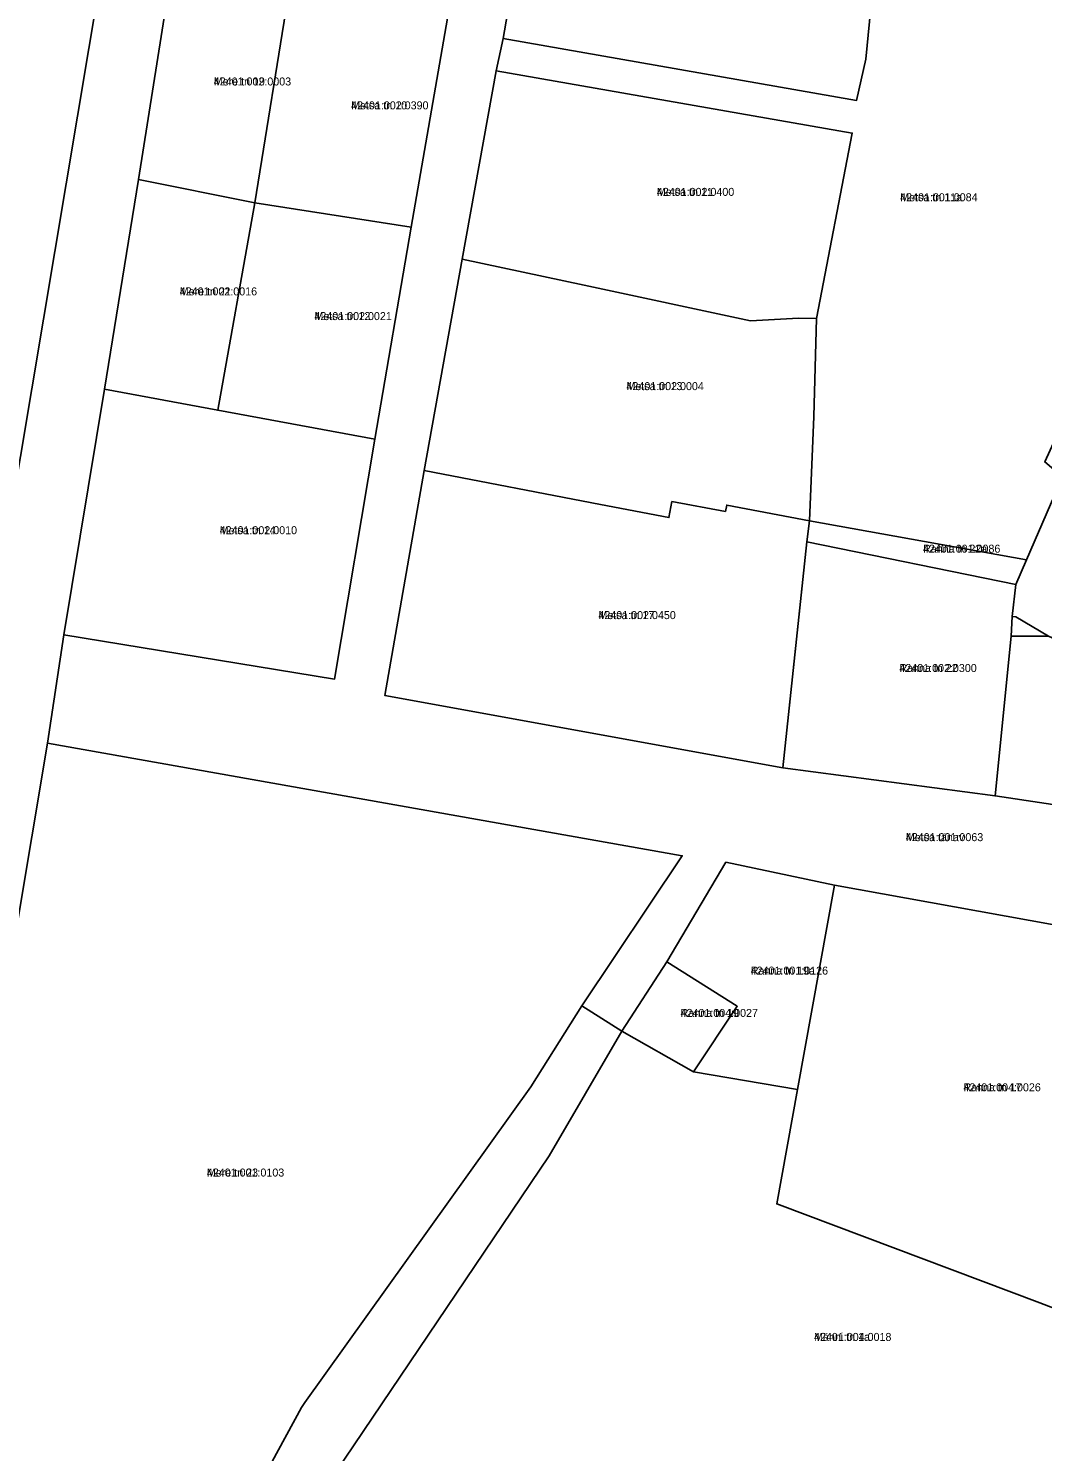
# Model space of a CAD drawing. Extents: x 595979 to 597983, y 6604231 to 6607350.
# Drawn here: x 596596.1 to 596786.2, y 6605469.2 to 6605736 of the extents above; entities that cross this region are included whole.
import ezdxf

# ---------------------------------------------------------------- set-up
doc = ezdxf.new("R2010")
doc.units = 0
for name, color, linetype in [('L_AADRESS', 7, 'Continuous'), ('PIIR', 7, 'Continuous'), ('TUNNUS', 7, 'Continuous')]:
    doc.layers.add(name, color=color, linetype=linetype)

msp = doc.modelspace()

# ---------------------------------------------------------------- linework, layer by layer
at = {"layer": 'PIIR'}
for points in [[(596695.91, 6606173.63), (596664.52, 6605976.79), (596663.07, 6605967.51), (596659.94, 6605968.22), (596650.85, 6605916.95), (596645.72, 6605885.35), (596645.06, 6605877.39), (596636.6, 6605826.7), (596630.08, 6605789.08), (596622.92, 6605747.16), (596616.69, 6605707.7), (596610.34, 6605668.35), (596602.72, 6605622.28), (596599.67, 6605601.99), (596540.44, 6605248.17)], [(596586.03, 6605605.02), (596609.5, 6605744.98), (596625.57, 6605841.47), (596638.15, 6605916.36), (596641.76, 6605919.43), (596645.62, 6605942.97), (596650.45, 6605972.44), (596649.26, 6605972.7), (596676, 6606132.91)], [(596692.66, 6605778.16), (596685.03, 6605734.09), (596683.77, 6605728.06), (596677.38, 6605692.71), (596670.24, 6605653.13), (596662.9, 6605610.91), (596737.48, 6605597.37), (596777.27, 6605592.09), (596818.04, 6605586.01), (596825.9, 6605604.77), (596837.28, 6605630.34), (596849.07, 6605656.32), (596860.73, 6605682.24), (596868.53, 6605699.81), (596873.49, 6605710.72), (596880.63, 6605726.43), (596886.61, 6605739.74)], [(596908.36, 6605765.26), (596891.49, 6605722.66), (596876.65, 6605686.44), (596875.04, 6605682.66), (596867.38, 6605665.51), (596858.76, 6605645.71), (596849.6, 6605616.3), (596846.89, 6605605.7), (596843.58, 6605582.38), (596828.15, 6605567.17), (596806.93, 6605570.9), (596806.33, 6605564.68), (596747.17, 6605575.34), (596726.8, 6605579.67), (596715.73, 6605560.98), (596707.32, 6605548), (596699.82, 6605552.72), (596718.61, 6605580.89), (596599.67, 6605601.99), (596602.72, 6605622.28), (596653.42, 6605613.98), (596660.98, 6605658.96), (596667.81, 6605698.76), (596674.62, 6605737.93)], [(596517.58, 6605763.43), (596609.5, 6605744.98), (596586.03, 6605605.02)], [(596540.44, 6605248.17), (596599.67, 6605601.99), (596718.61, 6605580.89), (596699.82, 6605552.72), (596690.25, 6605537.54), (596647.86, 6605478.35), (596647.27, 6605477.41), (596611.18, 6605411.05)], [(596611.18, 6605411.05), (596647.27, 6605477.41), (596647.86, 6605478.35), (596690.25, 6605537.54), (596699.82, 6605552.72), (596707.32, 6605548), (596693.66, 6605524.62), (596655.33, 6605467.74)]]:
    msp.add_lwpolyline(points, dxfattribs=at)
for points in [[(596783.16, 6605636.35), (596742.46, 6605643.65), (596743.26, 6605663.24), (596743.76, 6605681.63), (596750.48, 6605716.38), (596683.77, 6605728.06), (596685.03, 6605734.09), (596751.3, 6605722.5), (596753.04, 6605730.24), (596756.61, 6605766.92), (596781.4, 6605764.04), (596806.3, 6605761.22), (596821.32, 6605793.9), (596835.19, 6605774.82), (596828.35, 6605763.51), (596814.68, 6605734.88), (596800.26, 6605709.74), (596788.69, 6605683.33), (596797.85, 6605679.12), (596789.61, 6605661.31), (596786.57, 6605654.73), (596789.87, 6605651.91)], [(596692.66, 6605778.16), (596714.7, 6605774.77), (596717.73, 6605773.06), (596724.22, 6605771.51), (596756.61, 6605766.92), (596753.04, 6605730.24), (596751.3, 6605722.5), (596685.03, 6605734.09)], [(596622.92, 6605747.16), (596644.93, 6605743.23), (596638.51, 6605703.28), (596616.69, 6605707.7)], [(596674.62, 6605737.93), (596667.81, 6605698.76), (596638.51, 6605703.28), (596644.93, 6605743.23)], [(596683.77, 6605728.06), (596750.48, 6605716.38), (596743.76, 6605681.63), (596740.41, 6605681.67), (596731.43, 6605681.15), (596700.26, 6605687.85), (596677.38, 6605692.71)], [(596610.34, 6605668.35), (596616.69, 6605707.7), (596638.51, 6605703.28), (596631.55, 6605664.42)], [(596638.51, 6605703.28), (596667.81, 6605698.76), (596660.98, 6605658.96), (596631.55, 6605664.42)], [(596670.24, 6605653.13), (596677.38, 6605692.71), (596700.26, 6605687.85), (596731.43, 6605681.15), (596740.41, 6605681.67), (596743.76, 6605681.63), (596743.26, 6605663.24), (596742.46, 6605643.65), (596726.96, 6605646.64), (596726.73, 6605645.45), (596716.69, 6605647.28), (596716.13, 6605644.29), (596703.33, 6605646.71)], [(596610.34, 6605668.35), (596631.55, 6605664.42), (596660.98, 6605658.96), (596653.42, 6605613.98), (596602.72, 6605622.28)], [(596670.24, 6605653.13), (596703.33, 6605646.71), (596716.13, 6605644.29), (596716.69, 6605647.28), (596726.73, 6605645.45), (596726.96, 6605646.64), (596742.46, 6605643.65), (596741.96, 6605639.71), (596737.48, 6605597.37), (596662.9, 6605610.91)], [(596789.87, 6605651.91), (596837.28, 6605630.34), (596825.9, 6605604.77), (596787.26, 6605622.06), (596781.18, 6605625.67), (596780.49, 6605625.75), (596781.17, 6605631.75), (596783.16, 6605636.35)], [(596781.17, 6605631.75), (596741.96, 6605639.71), (596742.46, 6605643.65), (596783.16, 6605636.35)], [(596781.17, 6605631.75), (596780.49, 6605625.75), (596780.26, 6605622.05), (596777.27, 6605592.09), (596737.48, 6605597.37), (596740.65, 6605627.37), (596741.96, 6605639.71)], [(596787.26, 6605622.06), (596825.9, 6605604.77), (596818.04, 6605586.01), (596777.27, 6605592.09), (596780.26, 6605622.05)], [(596726.8, 6605579.67), (596747.17, 6605575.34), (596740.22, 6605537.04), (596720.74, 6605540.34), (596728.92, 6605552.67), (596715.73, 6605560.98)], [(596747.17, 6605575.34), (596806.33, 6605564.68), (596799.33, 6605491.84), (596785.62, 6605497.09), (596736.33, 6605515.61), (596740.22, 6605537.04)], [(596707.32, 6605548), (596720.74, 6605540.34), (596740.22, 6605537.04), (596736.33, 6605515.61), (596785.62, 6605497.09), (596799.33, 6605491.84), (596806.33, 6605564.68), (596806.93, 6605570.9), (596828.15, 6605567.17), (596804.06, 6605408.95), (596636.26, 6605434.88), (596646.27, 6605453.64), (596655.33, 6605467.74), (596693.66, 6605524.62)], [(596715.73, 6605560.98), (596728.92, 6605552.67), (596720.74, 6605540.34), (596707.32, 6605548)]]:
    msp.add_lwpolyline(points, close=True, dxfattribs=at)

# ---------------------------------------------------------------- texts
at = {"layer": 'L_AADRESS'}
for s, p in [('Mere tn 19', (596630.81, 6605725.3)), ('Metsa tn 10', (596656.56, 6605720.82)), ('Metsa tn 11', (596713.87, 6605704.6)), ('Metsa tn 11a', (596759.48, 6605703.59)), ('Mere tn 21', (596624.43, 6605685.94)), ('Metsa tn 12', (596649.68, 6605681.31)), ('Metsa tn 13', (596708.17, 6605668.18)), ('Metsa tn 14', (596631.92, 6605641.17)), ('Ranna tn 22a', (596763.75, 6605637.7)), ('Metsa tn 17', (596702.91, 6605625.25)), ('Ranna tn 22', (596759.32, 6605615.33)), ('Metsa tänav', (596760.54, 6605583.62)), ('Ranna tn 19a', (596731.45, 6605558.6)), ('Ranna tn 19', (596718.31, 6605550.66)), ('Ranna tn 17', (596771.33, 6605536.72)), ('Mere tn 23', (596629.52, 6605520.74)), ('Männi tn 1a', (596743.33, 6605489.92))]:
    msp.add_text(s, height=1.5, dxfattribs=at).set_placement(p)
at = {"layer": 'TUNNUS'}
for s, p in [('42401:002:0003', (596630.81, 6605725.3)), ('42401:002:0390', (596656.56, 6605720.82)), ('42401:002:0400', (596713.87, 6605704.6)), ('42401:001:0084', (596759.48, 6605703.59)), ('42401:002:0016', (596624.43, 6605685.94)), ('42401:002:0021', (596649.68, 6605681.31)), ('42401:002:0004', (596708.17, 6605668.18)), ('42401:002:0010', (596631.92, 6605641.17)), ('42401:001:0086', (596763.75, 6605637.7)), ('42401:002:0450', (596702.91, 6605625.25)), ('42401:002:0300', (596759.32, 6605615.33)), ('42401:001:0063', (596760.54, 6605583.62)), ('42401:001:0126', (596731.45, 6605558.6)), ('42401:004:0027', (596718.31, 6605550.66)), ('42401:004:0026', (596771.33, 6605536.72)), ('42401:001:0103', (596629.52, 6605520.74)), ('42401:004:0018', (596743.33, 6605489.92))]:
    msp.add_text(s, height=1.5, dxfattribs=at).set_placement(p)

doc.saveas('drawing.dxf')
